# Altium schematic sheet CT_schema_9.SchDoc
size 278 x 170 mm
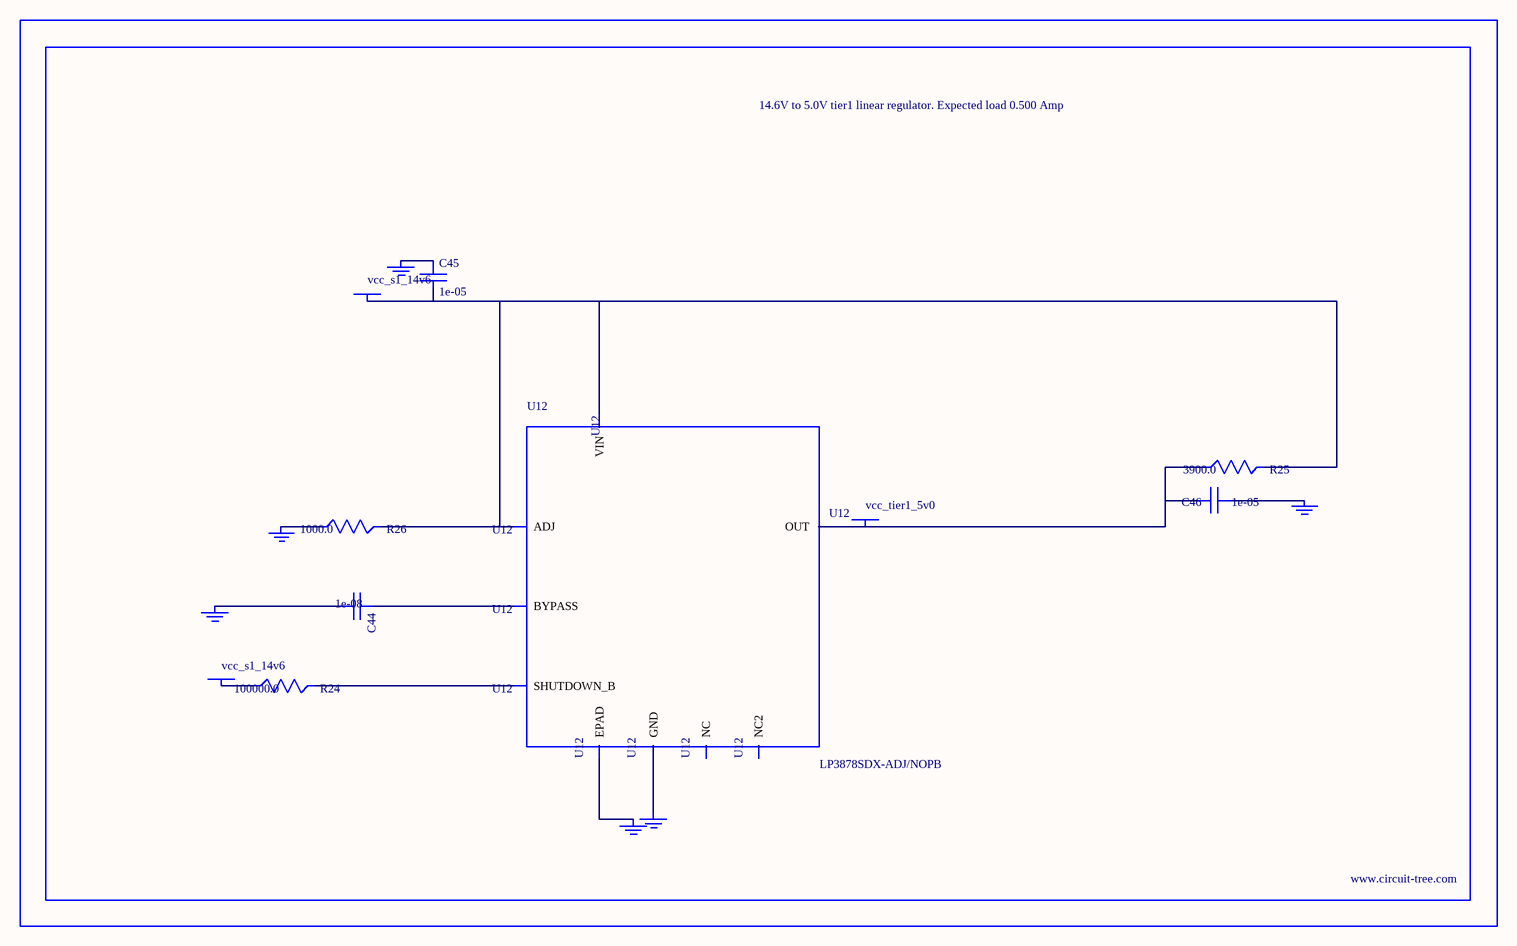
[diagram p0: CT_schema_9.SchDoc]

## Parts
BORDER8  (no value)
C44  1e-08  [C0402]
C45  1e-05  [C1210]
C46  1e-05  [C1210]
GND_INSTANCE_8_0  (no value)
GND_INSTANCE_8_1  (no value)
GND_INSTANCE_8_2  (no value)
GND_INSTANCE_8_3  (no value)
GND_INSTANCE_8_4  (no value)
GND_INSTANCE_8_5  (no value)
POWER_INSTANCE_8_0  vcc_s1_14v6
POWER_INSTANCE_8_1  vcc_s1_14v6
POWER_INSTANCE_8_2  vcc_tier1_5v0
R24  100000.0  [R0603]
R25  3900.0  [R0603]
R26  1000.0  [R0603]
U12  LP3878SDX-ADJ/NOPB  [WSON-8]

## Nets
NetC44_1: C44.1 U12.1(BYPASS)
NetC44_2: C44.2 GND_INSTANCE_8_0.0(GND)
NetC45_1: C45.1 GND_INSTANCE_8_1.0(GND)
NetC45_2: C45.2 POWER_INSTANCE_8_0.0(PWR) R25.2 R26.2 U12.4(VIN) U12.6(ADJ)
NetC46_1: C46.1 GND_INSTANCE_8_2.0(GND)
NetC46_2: C46.2 POWER_INSTANCE_8_2.0(PWR) R25.1 U12.5(OUT)
NetGND_INSTANCE_8_3_0: GND_INSTANCE_8_3.0(GND) R26.1
NetGND_INSTANCE_8_4_0: GND_INSTANCE_8_4.0(GND) U12.PAD(EPAD)
NetGND_INSTANCE_8_5_0: GND_INSTANCE_8_5.0(GND) U12.3(GND)
NetPOWER_INSTANCE_8_1_0: POWER_INSTANCE_8_1.0(PWR) R24.1
NetR24_2: R24.2 U12.8(SHUTDOWN_B)

Not connected (* = marked no-connect by the designer): U12 2(NC) 7(NC2)

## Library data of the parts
BORDER8 = BORDER_PAGE8
C44 = C0402C103K3RAC
C45 = C1210C106K5PACTU
C46 = GRM32DR61E106MA12L
GND_INSTANCE_8_0-GND_INSTANCE_8_5 = GND
POWER_INSTANCE_8_0-POWER_INSTANCE_8_2 = PWR
R24 = RC0603JR-07100KL
R25 = RC0603JR-073K9L
R26 = RC0603JR-071KL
